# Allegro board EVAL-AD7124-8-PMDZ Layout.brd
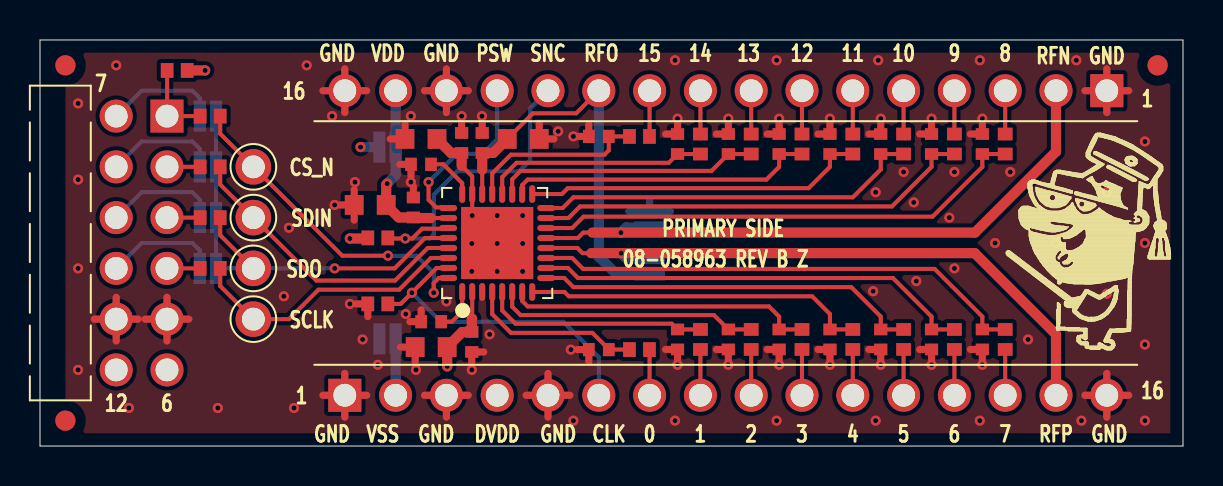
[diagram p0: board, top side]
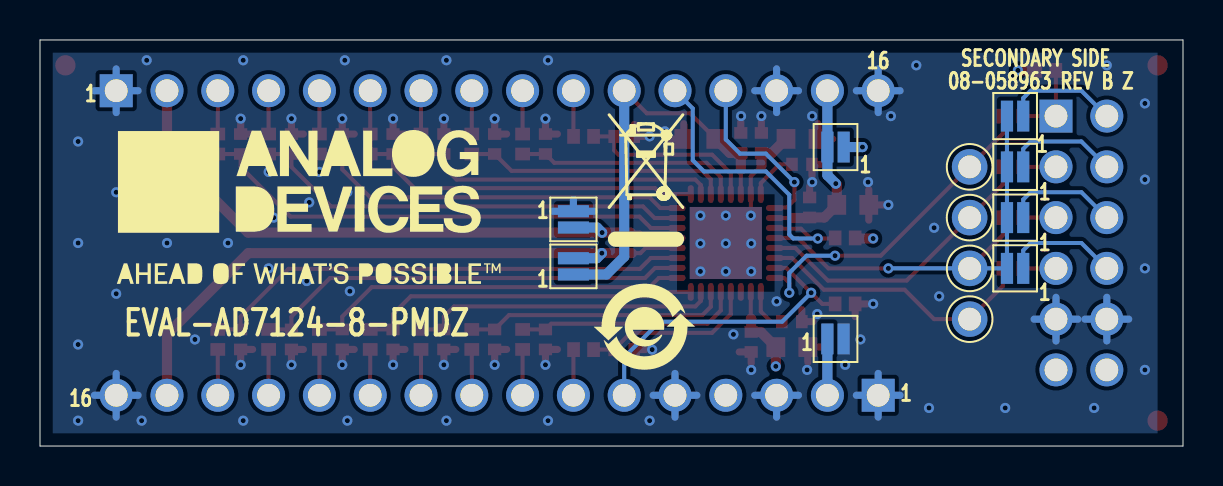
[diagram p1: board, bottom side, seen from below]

Outline 57.15 x 20.32 mm; copper layers: TOP, L2_GND, L3_PWR, BOTTOM. Coordinates in mm from the lower left corner of the outline.
Outline path: 0,20.32 0,0 57.15,0 57.15,20.32 0,20.32

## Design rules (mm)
constraint set DEFAULT: min track width 0.203
net group PWR: nets AVDD REFIN1_NEG REFIN1_POZ REFOUT

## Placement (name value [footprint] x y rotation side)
C1  1UF  [C0603]  19.56 4.95 180 top
C2  1UF  [C0603]  19.05 15.37 180 top
C3  0.1UF  [C0402]  21.59 5.21 270 top
C4  0.1UF  [C0402]  21.08 15.17 90 top
C5  0.1UF  [C0402]  18.67 11.94 90 top
C6  1UF  [C0603]  16.51 12.07 180 top
C7  0.1UF  [C0402]  19.56 6.22 180 top
C8  0.1UF  [C0402]  22.11 15.17 90 top
C9  0.1UF  [C0402]  19.05 14.1 180 top
C10  1UF  [C0603]  24.16 15.37 0 top
C11  0.1UF  [C0402]  27.94 15.49 180 top
C12  0.1UF  [C0402]  47.12 5.33 270 top
C13  0.1UF  [C0402]  31.88 15.11 90 top
C14  0.1UF  [C0402]  44.58 5.33 270 top
C15  0.1UF  [C0402]  34.42 15.11 90 top
C16  0.1UF  [C0402]  42.04 5.33 270 top
C17  0.1UF  [C0402]  36.96 15.11 90 top
C18  0.1UF  [C0402]  39.5 5.33 270 top
C19  0.1UF  [C0402]  39.5 15.11 90 top
C20  0.1UF  [C0402]  36.96 5.33 270 top
C21  0.1UF  [C0402]  42.04 15.11 90 top
C22  0.1UF  [C0402]  34.42 5.33 270 top
C23  0.1UF  [C0402]  44.58 15.11 90 top
C24  0.1UF  [C0402]  31.88 5.33 270 top
C25  0.1UF  [C0402]  47.12 15.11 90 top
C26  0.1UF  [C0402]  27.94 4.83 180 top
NOREF  -  []  29.24 30.18 0 top
NOREF#2  -  []  0 20.32 0 top
NOREF#3  -  []  -57.78 -9.91 0 top
NOREF#4  -  []  57.15 0 0 top
NOREF#5  -  [unnamed#2]  1.27 1.27 0 top
NOREF#6  -  []  -111.76 -173.99 0 top
NOREF#7  -  []  57.15 0 90 top
NOREF#8  -  []  -111.76 -173.99 0 top
NOREF#9  -  []  -111.76 -173.99 0 top
NOREF#10  -  [unnamed#2]  55.88 19.05 0 top
NOREF#11  -  []  -111.76 -173.99 0 top
NOREF#12  -  []  0 20.32 0 top
NOREF#13  -  []  -73.66 152.4 0 top
NOREF#14  -  []  3.81 3.81 0 top
NOREF#15  -  []  3.81 3.81 0 top
NOREF#16  -  []  0 0 0 top
NOREF#17  -  []  238.76 -11.43 0 top
NOREF#18  -  []  37.47 -8.25 270 top
NOREF#19  -  []  0 0 0 top
NOREF#20  -  []  -50.8 196.85 0 top
NOREF#21  -  [unnamed#2]  1.27 19.05 0 top
NOREF#22  -  []  43.69 11.94 180 bottom
NOREF#23  -  []  27.05 10.03 180 bottom
NOREF#24  -  []  26.92 5.97 180 bottom
P1  TSW-106-25-F-D-RA  [CNHDRRA2X6H240]  6.35 16.51 270 top
P2  TSW-116-07-T-S  [CNHDR1X16H335]  15.24 2.54 0 top
P3  TSW-116-07-T-S  [CNHDR1X16H335]  53.34 17.78 180 top
P4  -  [JPSLD02]  30.48 11.34 270 bottom
P5  -  [JPSLD02]  17.37 14.96 0 bottom
P6  -  [JPSLD02]  17.37 5.36 180 bottom
P7  -  [JPSLD02]  30.48 8.99 90 bottom
P8  -  [JPSLD02]  8.39 16.51 0 bottom
P9  -  [JPSLD02]  8.39 13.97 0 bottom
P10  -  [JPSLD02]  8.39 11.43 0 bottom
P11  -  [JPSLD02]  8.39 8.89 0 bottom
R1  10K  [R0402]  6.86 18.8 180 top
R2  10K  [R0402]  16.89 10.41 0 top
R3  10K  [R0402]  16.89 7.11 180 top
R4  1K  [R0402]  29.97 15.49 180 top
R5  1K  [R0402]  33.02 15.11 270 top
R6  1K  [R0402]  45.72 15.11 270 top
R7  1K  [R0402]  40.64 15.11 270 top
R8  1K  [R0402]  35.56 15.11 270 top
R9  1K  [R0402]  48.26 15.11 270 top
R10  1K  [R0402]  43.18 15.11 270 top
R11  1K  [R0402]  38.1 15.11 270 top
R12  1K  [R0402]  29.97 4.83 180 top
R13  1K  [R0402]  35.56 5.33 90 top
R14  1K  [R0402]  40.64 5.33 90 top
R15  1K  [R0402]  45.72 5.33 90 top
R16  1K  [R0402]  33.02 5.33 90 top
R17  1K  [R0402]  38.1 5.33 90 top
R18  1K  [R0402]  43.18 5.33 90 top
R19  1K  [R0402]  48.26 5.33 90 top
R20  0  [R0402]  8.51 13.97 180 top
R21  0  [R0402]  8.51 8.89 180 top
R22  0  [R0402]  8.51 16.51 180 top
R23  0  [R0402]  8.51 11.43 180 top
TP1  TESTPAD  [TPC75D45]  10.67 13.97 0 top
TP2  TESTPAD  [TPC75D45]  10.67 11.43 0 top
TP3  TESTPAD  [TPC75D45]  10.67 8.89 0 top
TP4  TESTPAD  [TPC75D45]  10.67 6.35 0 top
U1  AD7124-8BCPZ  [QFN32_5X5_PAD3_6X3_6]  22.86 10.16 0 top

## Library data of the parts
C1 C2 C6 C10 = CAP: User Part Number: UPN; Tolerance: 10; alternate symbols: (); part number: CAP_SM-1UF,25V,10,E033832,C0603; tolerance: 10
C3-C5 C7-C9 C11-C26 = CAP: User Part Number: UPN; Tolerance: 10; alternate symbols: (); part number: CAP_SM-0.1UF,25V,10,E026964,C0402; tolerance: 10
P1 = CN12P_V3: User Part Number: UPN; Tolerance: N/A; alternate symbols: (); part number: CN12P_V3_TH-TSW-106-25-F-D-RA,E018495,CNHDRRA2X6H240; tolerance: N/A
P2 P3 = CN16P: User Part Number: UPN; Tolerance: N/A; alternate symbols: (); part number: CN16P_TH-TSW-116-07-T-S,E025686,CNHDR1X16H335; tolerance: N/A
P4-P11 = NC2P: User Part Number: UPN; Tolerance: N/A; alternate symbols: (); part number: NC2P_SM-JPSLD02,E006230,JPSLD02; tolerance: N/A
R1-R3 = RES: User Part Number: UPN; Tolerance: 1; alternate symbols: (R0402L,R0402L_ALT); part number: RES_SM-10K,E003751,1/10W,1,R0402; tolerance: 1
R4-R19 = RES: User Part Number: UPN; Tolerance: 1; alternate symbols: (R0402L,R0402L_ALT); part number: RES_SM-1K,E003763,1/10W,1,R0402; tolerance: 1
R20-R23 = RES: User Part Number: UPN; Tolerance: 5; alternate symbols: (R0402L,R0402L_ALT); part number: RES_SM-0,E003438,N/A,5,R0402; tolerance: 5
TP1-TP4 = NCTESTPAD: Tolerance: N/A; User Part Number: UPN; alternate symbols: (); part number: NCTESTPAD_TH-TESTPAD,E004910,TPC75D45; tolerance: N/A
U1 = AD7124_8: Tolerance: N/A; User Part Number: UPN; alternate symbols: (); part number: AD7124_8_SM-AD7124-8BCPZ,E023649,QFN32_5X5_PAD3_6X3_6; tolerance: N/A

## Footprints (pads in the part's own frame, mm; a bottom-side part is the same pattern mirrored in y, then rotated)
C0402
  rect 0.584x0.66 smd: 1(-0.5,0) 2(0.5,0)
C0603
  rect 0.94x0.991 smd: 1(-0.8,0) 2(0.8,0)
CNHDR1X16H335
  rect 1.651x1.651 hole 1.143: 1(0,0)
  round 1.651 hole 1.143: 2(2.54,0) 3(5.08,0) 4(7.62,0) 5(10.16,0) 6(12.7,0) 7(15.24,0) 8(17.78,0) 9(20.32,0) 10(22.86,0) 11(25.4,0) 12(27.94,0) 13(30.48,0) 14(33.02,0) 15(35.56,0) 16(38.1,0)
CNHDRRA2X6H240
  rect 1.651x1.651 hole 1.143: 1(0,0)
  round 1.651 hole 1.143: 2(2.54,0) 3(5.08,0) 4(7.62,0) 5(10.16,0) 6(12.7,0) 7(0,-2.54) 8(2.54,-2.54) 9(5.08,-2.54) 10(7.62,-2.54) 11(10.16,-2.54) 12(12.7,-2.54)
JPSLD02
  rect 0.61x1.549 smd: 1(-0.406,0) 2(0.406,0)
QFN32_5X5_PAD3_6X3_6
  oval 0.305x0.889 smd: 1(-1.75,-2.451) 2(-1.25,-2.451) 3(-0.75,-2.451) 4(-0.25,-2.451) 5(0.25,-2.451) 6(0.75,-2.451) 7(1.25,-2.451) 8(1.75,-2.451) 17(1.75,2.451) 18(1.25,2.451) 19(0.75,2.451) 20(0.25,2.451) 21(-0.25,2.451) 22(-0.75,2.451) 23(-1.25,2.451) 24(-1.75,2.451)
  oval 0.889x0.305 smd: 9(2.451,-1.75) 10(2.451,-1.25) 11(2.451,-0.75) 12(2.451,-0.25) 13(2.451,0.25) 14(2.451,0.75) 15(2.451,1.25) 16(2.451,1.75) 25(-2.451,1.75) 26(-2.451,1.25) 27(-2.451,0.75) 28(-2.451,0.25) 29(-2.451,-0.25) 30(-2.451,-0.75) 31(-2.451,-1.25) 32(-2.451,-1.75)
  rect 3.607x3.607 smd: PAD(0,0)
R0402
  rect 0.635x0.737 smd: 1(-0.5,0) 2(0.5,0)
TPC75D45
  round 1.778 hole 1.143: 1(0,0)
unnamed#2
  round 1.016 smd: (0,0)

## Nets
AVDD: C5.1 C6.1 P3.15 P5.2(N2) U1.26
AVSS: C2.1 C4.1 P2.2 P6.1 U1.23 U1.PAD
GND: C1.2(N2) C2.2(N2) C3.2(N2) C4.2(N2) C5.2(N2) C6.2(N2) C7.2(N2) C8.2(N2) C9.2(N2) C10.2(N2) C11.2(N2) C12.2(N2) C13.2(N2) C14.2(N2) C15.2(N2) C16.2(N2) C17.2(N2) C18.2(N2) C19.2(N2) C20.2(N2) C21.2(N2) C22.2(N2) C23.2(N2) C24.2(N2) C25.2(N2) C26.2(N2) P1.5 P1.11 P2.1 P2.3 P2.5 P2.16 P3.1 P3.14 P3.16 P4.1 P6.2(N2) R3.2(N2) U1.3
AIN0: C26.1 R12.2(N2) U1.4
AIN1: C24.1 R16.2(N2) U1.5
AIN2: C22.1 R13.2(N2) U1.6
AIN3: C20.1 R17.2(N2) U1.7
AIN4: C18.1 R14.2(N2) U1.8
AIN5: C16.1 R18.2(N2) U1.9
AIN6: C14.1 R15.2(N2) U1.10
AIN7: C12.1 R19.2(N2) U1.11
AIN8: C25.1 R9.2(N2) U1.14
AIN9: C23.1 R6.2(N2) U1.15
AIN10: C21.1 R10.2(N2) U1.16
AIN11: C19.1 R7.2(N2) U1.17
AIN12: C17.1 R11.2(N2) U1.18
AIN13: C15.1 R8.2(N2) U1.19
AIN14: C13.1 R5.2(N2) U1.20
AIN15: C11.1 R4.2(N2) U1.21
CLK: P2.6 R3.1 U1.31
CS_N: R22.1 TP1.1(N1) U1.32
IOVDD: C1.1 C3.1 P1.6 P1.12(VCC2) P2.4 P5.1 R1.1 R2.1 U1.2
PSW: P3.13 U1.25
REFIN1_NEG: P3.2 P4.2(N2) U1.13
REFIN1_POZ: P2.15 P7.2(N2) U1.12
REFOUT: C8.1 C10.1 P3.11 P7.1 U1.22
SCLK: R21.1 TP4.1(N1) U1.30
SDIN: R20.1 TP2.1(N1) U1.29
SDO: P8.2(N2) P9.2(N2) P10.2(N2) P11.2(N2) R23.1 TP3.1(N1) U1.28
SYNC_N: P3.12 R2.2(N2) U1.27(SYNC_N)
UNNAMED_2_AD71248_I96_REGCAPA: C9.1 U1.24
UNNAMED_2_AD71248_I96_REGCAPD: C7.1 U1.1
UNNAMED_2_CN12PV3_I17_P1: P1.1 R1.2(N2) R22.2(N2)
UNNAMED_2_CN12PV3_I17_P2: P1.2 R20.2(N2)
UNNAMED_2_CN12PV3_I17_P3: P1.3 R23.2(N2)
UNNAMED_2_CN12PV3_I17_P4: P1.4 R21.2(N2)
UNNAMED_2_CN12PV3_I17_P7: P1.7 P8.1
UNNAMED_2_CN12PV3_I17_P8: P1.8 P9.1
UNNAMED_2_CN12PV3_I17_P9: P1.9 P10.1
UNNAMED_2_CN12PV3_I17_P10: P1.10 P11.1
UNNAMED_2_CN16P_I10_N7: P2.7 R12.1
UNNAMED_2_CN16P_I10_N8: P2.8 R16.1
UNNAMED_2_CN16P_I10_N9: P2.9(N9) R13.1
UNNAMED_2_CN16P_I10_N10: P2.10 R17.1
UNNAMED_2_CN16P_I10_N11: P2.11 R14.1
UNNAMED_2_CN16P_I10_N12: P2.12 R18.1
UNNAMED_2_CN16P_I10_N13: P2.13 R15.1
UNNAMED_2_CN16P_I10_N14: P2.14 R19.1
UNNAMED_2_CN16P_I27_N3: P3.3 R9.1
UNNAMED_2_CN16P_I27_N4: P3.4 R6.1
UNNAMED_2_CN16P_I27_N5: P3.5 R10.1
UNNAMED_2_CN16P_I27_N6: P3.6 R7.1
UNNAMED_2_CN16P_I27_N7: P3.7 R11.1
UNNAMED_2_CN16P_I27_N8: P3.8 R8.1
UNNAMED_2_CN16P_I27_N9: P3.9(N9) R5.1
UNNAMED_2_CN16P_I27_N10: P3.10 R4.1

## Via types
v1: diameter 0.508, hole 0.254, TOP to BOTTOM, 94 vias

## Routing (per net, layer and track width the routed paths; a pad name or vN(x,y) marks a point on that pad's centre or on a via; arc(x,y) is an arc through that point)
AVDD: length 13.7
  TOP w0.203: U1.26 19.54,11.41
  TOP w0.508: v1(17.36,13.13) 17.31,13.08 C6.1 17.94,11.44 C5.1 18.7,11.41 19.54,11.41
  L3_PWR w0.356: 16.69,17.78 P3.15 ; P3.15 17.78,18.87 ; P3.15 17.78,16.69 ; P3.15 18.87,17.78
  BOTTOM w0.508: v1(17.36,13.13) 17.78,13.55 P5.2 P3.15
AVSS: length 16.7
  TOP w0.203: v1(21.61,11.53) U1.23 21.61,13.5 21.08,14.02
  TOP w0.508: 21.08,14.02 C4.1 20.55,14.67 C2.1
  L3_PWR w0.508: v1(21.59,8.74) 21.59,6.6 20.68,5.69 18.57,5.69 17.78,4.9 P2.2
  BOTTOM w0.508: P6.1 P2.2
  vias: v1(21.59,10.13) v1(22.86,11.53) v1(22.86,10.13) v1(22.86,8.74) v1(24.13,11.53) v1(24.13,10.13) v1(24.13,8.74)
GND: length 149
  TOP w0.356: 31.88,4.27 C24.2 31.28,4.83 ; 42.04,4.27 C16.2 41.44,4.83 ; 6.35,5.26 P1.5 ; P1.5 5.26,6.35 ; P1.5 7.44,6.35 ; P1.5 6.35,7.44 ; 15.81,7.11 R3.2 16.39,6.48 ; 27.44,4.23 C26.2 26.88,4.83 ; 41.44,15.61 C21.2 42.04,16.17 ; 34.42,4.27 C22.2 33.82,4.83 ; 20.32,1.45 P2.3 ; P2.3 19.23,2.54 ; P2.3 21.41,2.54 ; 36.36,4.83 C20.2 36.96,4.27 ; 44.58,4.27 C14.2 43.98,4.83 ; 44.58,16.17 C23.2 43.98,15.61 ; 24.96,16.13 C10.2 25.7,15.37 ; P3.14 21.41,17.78 ; P3.14 20.32,16.69 ; P3.14 19.23,17.78 ; P3.14 20.32,18.87 ; 2.72,6.35 P1.11 ; P1.11 3.81,5.26 ; P1.11 3.81,7.44 ; P1.11 4.9,6.35 ; 36.36,15.61 C17.2 36.96,16.17 ; C8.2 22.11,16.23 ; 17.99,14.1 C9.2 18.55,13.5 ; P3.1 54.43,17.78 ; P3.1 53.34,18.87 ; P3.1 53.34,16.69 ; P3.1 52.25,17.78 ; 53.34,1.45 P2.16 ; P2.16 52.25,2.54 ; P2.16 54.43,2.54 ; P2.16 53.34,3.63 ; 34.42,16.17 C15.2 33.82,15.61 ; C5.2 18.67,13 ; C4.2 21.08,16.23 ; P2.5 25.4,3.63 ; P2.5 26.49,2.54 ; P2.5 24.31,2.54 ; P2.5 25.4,1.45 ; 14.15,2.54 P2.1 ; P2.1 16.33,2.54 ; P2.1 15.24,3.63 ; P2.1 15.24,1.45 ; 15.71,11.3 C6.2 ; C6.2 14.97,12.07 ; C6.2 15.71,12.83 ; 18.02,4.95 C1.2 18.76,4.19 ; 47.12,4.27 C12.2 46.52,4.83 ; P3.16 16.33,17.78 ; P3.16 15.24,16.69 ; P3.16 15.24,18.87 ; P3.16 14.15,17.78 ; 38.9,4.83 C18.2 39.5,4.27 ; 22.19,4.71 C3.2 21.59,4.15 ; 26.88,15.49 C11.2 27.44,16.09 ; 19.06,6.82 C7.2 18.5,6.22 ; 38.9,15.61 C19.2 39.5,16.17 ; 17.51,15.37 C2.2 18.25,16.13 ; 31.28,15.61 C13.2 31.88,16.17 ; 47.12,16.17 C25.2 46.52,15.61
  L2_GND w0.356: P2.3 21.41,2.54 ; P2.3 20.32,1.45 ; P2.3 19.23,2.54 ; P1.11 4.9,6.35 ; P1.11 3.81,7.44 ; P1.11 2.72,6.35 ; P1.11 3.81,5.26 ; P3.1 54.43,17.78 ; P3.1 53.34,18.87 ; P3.1 52.25,17.78 ; P3.1 53.34,16.69 ; 15.24,1.45 P2.1 ; P2.1 14.15,2.54 ; P2.1 16.33,2.54 ; P2.1 15.24,3.63 ; P2.16 54.43,2.54 ; P2.16 53.34,1.45 ; P2.16 52.25,2.54 ; P2.16 53.34,3.63 ; P1.5 6.35,7.44 ; P1.5 7.44,6.35 ; P1.5 6.35,5.26 ; P1.5 5.26,6.35 ; P3.14 21.41,17.78 ; P3.14 20.32,16.69 ; P3.14 19.23,17.78 ; P3.14 20.32,18.87 ; 14.15,17.78 P3.16 ; P3.16 16.33,17.78 ; P3.16 15.24,18.87 ; P3.16 15.24,16.69 ; 24.31,2.54 P2.5 ; P2.5 25.4,1.45 ; P2.5 26.49,2.54 ; P2.5 25.4,3.63
  BOTTOM w0.356: P3.14 20.32,18.87 ; P3.14 21.41,17.78 ; P3.14 20.32,16.69 ; P3.14 19.23,17.78 ; 24.31,2.54 P2.5 ; P2.5 25.4,1.45 ; P2.5 25.4,3.63 ; P2.5 26.49,2.54 ; 19.23,2.54 P2.3 ; P2.3 20.32,1.45 ; P2.3 21.41,2.54 ; P3.1 53.34,18.87 ; P3.1 53.34,16.69 ; P3.1 54.43,17.78 ; P3.1 52.25,17.78 ; P2.16 53.34,3.63 ; P2.16 54.43,2.54 ; P2.16 52.25,2.54 ; P2.16 53.34,1.45 ; 15.24,1.45 P2.1 ; P2.1 16.33,2.54 ; P2.1 14.15,2.54 ; P2.1 15.24,3.63 ; 6.35,5.26 P1.5 ; P1.5 7.44,6.35 ; P1.5 5.26,6.35 ; P1.5 6.35,7.44 ; P1.11 4.9,6.35 ; P1.11 3.81,5.26 ; P1.11 3.81,7.44 ; P1.11 2.72,6.35 ; P4.1 31.52,11.75 ; P4.1 29.44,11.75 ; P4.1 30.48,12.32 ; 14.15,17.78 P3.16 ; P3.16 16.33,17.78 ; P3.16 15.24,16.69 ; P3.16 15.24,18.87
  vias: v1(1.91,17.14) v1(1.91,13.34) v1(1.91,8.89) v1(1.91,3.81) v1(3.81,19.05) v1(4.45,1.91) v1(8.89,1.91) v1(12.19,7.49) v1(12.45,10.92) v1(12.7,1.91) v1(13.34,19.05) v1(14.61,16.51) v1(14.73,12.07) v1(15.49,7.11) v1(15.75,13.21) v1(16.13,5.33) v1(16.89,4.06) v1(18.29,6.6) v1(18.54,16.51) v1(18.54,13.21) v1(18.8,3.81) v1(20.32,7.24) v1(21.08,16.51) v1(21.59,3.81) v1(22.1,16.51) v1(22.48,5.59) v1(25.91,15.75) v1(26.54,4.83) v1(26.67,15.49) v1(26.67,1.27) v1(31.75,19.3) v1(31.75,1.27) v1(31.88,16.38) v1(31.88,4.06) v1(34.42,16.38) v1(34.42,4.06) v1(36.83,19.3) v1(36.83,1.27) v1(36.96,16.38) v1(36.96,4.06) v1(39.5,16.38) v1(39.5,4.06) v1(41.66,7.75) v1(41.78,12.7) v1(41.78,1.27) v1(41.91,19.3) v1(42.04,16.38) v1(42.04,4.06) v1(43.18,13.72) v1(43.69,12.19) v1(43.82,8.26) v1(44.58,16.38) v1(44.58,4.06) v1(45.47,11.43) v1(45.72,13.72) v1(45.72,8.89) v1(46.99,19.3) v1(46.99,1.27) v1(47.12,16.38) v1(47.12,4.06) v1(47.75,10.16) v1(48.51,13.72) v1(49.4,5.33) v1(50.8,10.16) v1(51.82,19.3) v1(52.07,1.27) v1(53.34,12.7) v1(53.34,7.62) v1(55.25,15.24) v1(55.25,10.16) v1(55.25,5.08) v1(55.25,1.27)
AIN0: length 8.7
  TOP w0.203: U1.4 22.61,6.6 23.55,5.66 27.62,5.66 28.44,4.84 C26.1 R12.2
AIN1: length 11.2
  TOP w0.203: R16.2 C24.1 31.59,6.12 23.77,6.12 23.11,6.79 U1.5
AIN2: length 13.2
  TOP w0.203: U1.6 23.61,6.97 24.03,6.55 33.7,6.55 C22.1 R13.2
AIN3: length 15.4
  TOP w0.203: R17.2 C20.1 36.96,6.48 36.45,6.98 24.38,6.98 24.11,7.26 U1.7
AIN4: length 17.3
  TOP w0.203: U1.8 26.23,7.71 26.44,7.49 38.61,7.49 39.5,6.6 C18.1 R14.2
AIN5: length 19.3
  TOP w0.203: U1.9 26.21,8.41 26.67,7.95 40.56,7.95 42.04,6.48 C16.1 R18.2
AIN6: length 22.1
  TOP w0.203: U1.10 26.4,8.91 26.9,8.41 42.65,8.41 44.58,6.48 C14.1 R15.2
AIN7: length 24.8
  TOP w0.203: U1.11 26.61,9.41 27.15,8.86 44.73,8.86 47.12,6.48 C12.1 R19.2
AIN8: length 24.9
  TOP w0.203: U1.14 26.61,10.91 27.18,11.48 44.63,11.48 47.12,13.97 C25.1 R9.2
AIN9: length 22.1
  TOP w0.203: U1.15 26.42,11.41 27,11.99 42.6,11.99 44.58,13.97 C23.1 R6.2
AIN10: length 19.4
  TOP w0.203: R10.2 C21.1 42.04,13.84 40.64,12.45 26.67,12.45 26.13,11.91 U1.16
AIN11: length 17.2
  TOP w0.203: U1.17 26.1,12.61 26.39,12.9 38.43,12.9 39.5,13.97 C19.1 R7.2
AIN12: length 15.5
  TOP w0.203: U1.18 24.11,13.06 24.38,13.34 36.32,13.34 36.96,13.97 C17.1 R11.2
AIN13: length 13.2
  TOP w0.203: R8.2 C15.1 33.57,13.77 24.03,13.77 23.61,13.35 U1.19
AIN14: length 11.2
  TOP w0.203: U1.20 23.11,13.46 23.83,14.17 31.44,14.17 C13.1 R5.2
AIN15: length 9.1
  TOP w0.203: R4.2 C11.1 28.44,14.8 28.22,14.58 23.55,14.58 22.61,13.64 U1.21
CLK: length 16.4
  TOP w0.203: U1.31 19.83,8.91 v1(18.59,7.67) 18.03,7.11 R3.1
  BOTTOM w0.203: v1(18.59,7.67) 20.04,6.22 26.16,6.22 27.94,4.45 P2.6
CS_N: length 16.7
  TOP w0.203: R22.1 9.01,15.63 TP1.1 15.11,9.53 v1(17.4,9.53) ; U1.32 19.94,8.41 19.68,8.15 v1(19.68,7.67)
  BOTTOM w0.203: v1(17.4,9.53) 18.82,9.53 19.68,8.66 v1(19.68,7.67)
IOVDD: length 20.4
  TOP w0.203: 21.61,6.38 U1.2
  TOP w0.508: v1(20.36,3.99) 20.36,4.95 C1.1 21.11,5.71 C3.1 21.59,6.36 21.61,6.38 ; R2.1 16.36,10.38 v1(15.49,10.38) ; R1.1 v1(8.26,18.8)
  L3_PWR w0.356: P2.4 23.95,2.54 ; P2.4 22.86,1.45 ; P2.4 22.86,3.63 ; P2.4 21.77,2.54 ; P1.12 3.81,4.9 ; P1.12 4.9,3.81 ; P1.12 2.72,3.81 ; P1.12 3.81,2.72 ; P1.6 7.44,3.81 ; P1.6 6.35,4.9 ; P1.6 5.26,3.81 ; P1.6 6.35,2.72
  BOTTOM w0.508: P5.1 v1(16.03,14.96)
PSW: length 8.8
  TOP w0.203: U1.25 20.38,11.94 19.81,11.94 19.43,12.32 v1(19.43,13.21)
  BOTTOM w0.203: P3.13 22.86,15.34 22.15,14.63 20.85,14.63 v1(19.43,13.21)
REFIN1_NEG: length 31.9
  TOP w0.203: U1.13 26.89,10.41 27.17,10.68 27.62,10.68
  TOP w0.508: 27.62,10.68 v1(29.04,10.68) 46.75,10.68 50.8,14.73 P3.2
  BOTTOM w0.508: P4.2 29.3,10.93 v1(29.04,10.68)
REFIN1_POZ: length 31.9
  TOP w0.203: U1.12 26.87,9.91 27.13,9.65 27.56,9.65
  TOP w0.508: P2.15 50.8,5.59 46.74,9.65 v1(29.06,9.65) 27.56,9.65
  BOTTOM w0.508: P7.2 29.31,9.4 v1(29.06,9.65)
REFOUT: length 20.4
  TOP w0.203: P3.11 26.81,16.65 24.64,16.65 C10.1 ; 22.11,13.83 U1.22
  TOP w0.508: 22.11,13.83 C8.1 22.66,14.67 C10.1
  BOTTOM w0.508: P3.11 27.94,9.47 28.83,8.59 P7.1
SCLK: length 14.2
  TOP w0.203: R21.1 9.01,8.01 TP4.1 12.45,6.35 13.92,7.82 17.96,7.82 19.54,9.41 U1.30
SDIN: length 14.9
  TOP w0.203: R20.1 9.01,13.09 TP2.1 13.82,8.28 17.75,8.28 19.38,9.91 U1.29
SDO: length 23.1
  TOP w0.203: TP3.1 9.01,10.55 R23.1 ; U1.28 19.25,10.41 17.73,8.89 v1(14.73,8.89)
  BOTTOM w0.203: v1(14.73,8.89) TP3.1 P11.2 P10.2 P9.2 P8.2
SYNC_N: length 16.1
  TOP w0.203: R2.2 17.42,10.38 v1(18.26,10.38) 18.61,10.38 19.11,10.88 20.38,10.88 U1.27
  BOTTOM w0.203: P3.12 24.51,16.89 24.51,14.3 23.95,13.74 20.85,13.74 19.68,12.57 19.68,10.59 19.48,10.38 v1(18.26,10.38)
UNNAMED_2_AD71248_I96_REGCAPA: length 2.5
  TOP w0.203: C9.1 20.17,14.1 21.11,13.15 U1.24
UNNAMED_2_AD71248_I96_REGCAPD: length 2.2
  TOP w0.203: U1.1 21.11,6.73 20.6,6.22 C7.1
UNNAMED_2_CN12PV3_I17_P1: length 3.9
  TOP w0.203: R1.2 6.36,16.52 P1.1 R22.2
UNNAMED_2_CN12PV3_I17_P2: length 1.7
  TOP w0.203: P1.2 R20.2
UNNAMED_2_CN12PV3_I17_P3: length 1.7
  TOP w0.203: P1.3 R23.2
UNNAMED_2_CN12PV3_I17_P4: length 1.7
  TOP w0.203: P1.4 R21.2
UNNAMED_2_CN12PV3_I17_P7: length 5.8
  BOTTOM w0.203: P8.1 7.99,17.41 7.62,17.78 5.08,17.78 P1.7
UNNAMED_2_CN12PV3_I17_P8: length 5.8
  BOTTOM w0.203: P1.8 5.08,15.24 7.62,15.24 7.99,14.87 P9.1
UNNAMED_2_CN12PV3_I17_P9: length 5.8
  BOTTOM w0.203: P1.9 5.08,12.7 7.62,12.7 7.99,12.33 P10.1
UNNAMED_2_CN12PV3_I17_P10: length 5.8
  BOTTOM w0.203: P1.10 5.08,10.16 7.62,10.16 7.99,9.79 P11.1
UNNAMED_2_CN16P_I10_N7: length 2.3
  TOP w0.203: P2.7 30.48,4.82 R12.1
UNNAMED_2_CN16P_I10_N8: length 2.3
  TOP w0.203: R16.1 P2.8
UNNAMED_2_CN16P_I10_N9: length 2.3
  TOP w0.203: R13.1 P2.9
UNNAMED_2_CN16P_I10_N10: length 2.3
  TOP w0.203: R17.1 P2.10
UNNAMED_2_CN16P_I10_N11: length 2.3
  TOP w0.203: R14.1 P2.11
UNNAMED_2_CN16P_I10_N12: length 2.3
  TOP w0.203: R18.1 P2.12
UNNAMED_2_CN16P_I10_N13: length 2.3
  TOP w0.203: R15.1 P2.13
UNNAMED_2_CN16P_I10_N14: length 2.3
  TOP w0.203: R19.1 P2.14
UNNAMED_2_CN16P_I27_N3: length 2.2
  TOP w0.203: R9.1 P3.3
UNNAMED_2_CN16P_I27_N4: length 2.2
  TOP w0.203: P3.4 R6.1
UNNAMED_2_CN16P_I27_N5: length 2.2
  TOP w0.203: P3.5 R10.1
UNNAMED_2_CN16P_I27_N6: length 2.2
  TOP w0.203: P3.6 R7.1
UNNAMED_2_CN16P_I27_N7: length 2.2
  TOP w0.203: P3.7 R11.1
UNNAMED_2_CN16P_I27_N8: length 2.2
  TOP w0.203: P3.8 R8.1
UNNAMED_2_CN16P_I27_N9: length 2.2
  TOP w0.203: P3.9 R5.1
UNNAMED_2_CN16P_I27_N10: length 2.3
  TOP w0.203: P3.10 30.48,15.5 R4.1

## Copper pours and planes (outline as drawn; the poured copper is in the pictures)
AVDD on L3_PWR: 1.27,19.68 56.51,19.68 56.51,0.64 1.27,0.64
AVSS on BOTTOM: 21.06,11.96 21.06,8.36 24.66,8.36 24.66,11.96
GND on TOP: 1.27,19.68 56.51,19.68 56.51,0.64 1.27,0.64 ; 6 cut-outs
GND on BOTTOM: 1.27,19.68 56.51,19.68 56.51,0.64 1.27,0.64 ; 2 cut-outs
GND on L2_GND: 1.27,19.68 56.51,19.68 56.51,0.64 1.27,0.64
IOVDD on L3_PWR: 1.27,19.68 1.27,0.64 24.36,0.64 24.36,3.71 23.09,4.98 20.37,4.98 19.43,5.92 19.43,11 19.02,11.4 16.84,11.4 16.38,11.86 16.38,16 15.82,16.56 15.82,19.68

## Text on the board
Ref Des/Silkscreen Bottom: EVAL-AD7124-8-PMDZ
User.Comments: 5.    DO NOT TRIM EXCESS PINS OF P2 AND P3 (P/N TSW-116-07-T-S)
Ref Des/Silkscreen Top: SDO | CS_N | SDIN | SCLK | GND | VSS | VDD | PSW | DVDD | SNC | RFO | CLK | 15 | 0 | 14 | 1 | 13 | 2 | 12 | 3 | 11 | 4 | 10 | 5 | 9 | 6 | 8 | 7 | RFN | RFP
PAGE_OUTLINE: B | AS PER ECR-092843 | 27JAN2020 | M. SUCIU
DIMENSION: " " | REF | DIA MAX
User.13: 1. SHORT P4, P5, P6, P7, AND P8 USING SOLDER BLOB. | ASSEMBLY NOTES:
User.23: L2 GND | 08-      -07
User.24: L3 PWR | 08-      -08
User.45: FIGURE | SIZE | 10.0 | 45.0 | PLATED | DRILL CHART: TOP to BOTTOM | ALL UNITS ARE IN MILS | QTY | 94 | 48 | TOLERANCE/NOTES
